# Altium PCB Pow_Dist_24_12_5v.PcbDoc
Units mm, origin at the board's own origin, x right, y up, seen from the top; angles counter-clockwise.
Board outline 255.4 x 262.89 mm, 2 copper layers (Top Layer, Bottom Layer); 118 components, 61 nets, 248 pads, 0 vias.
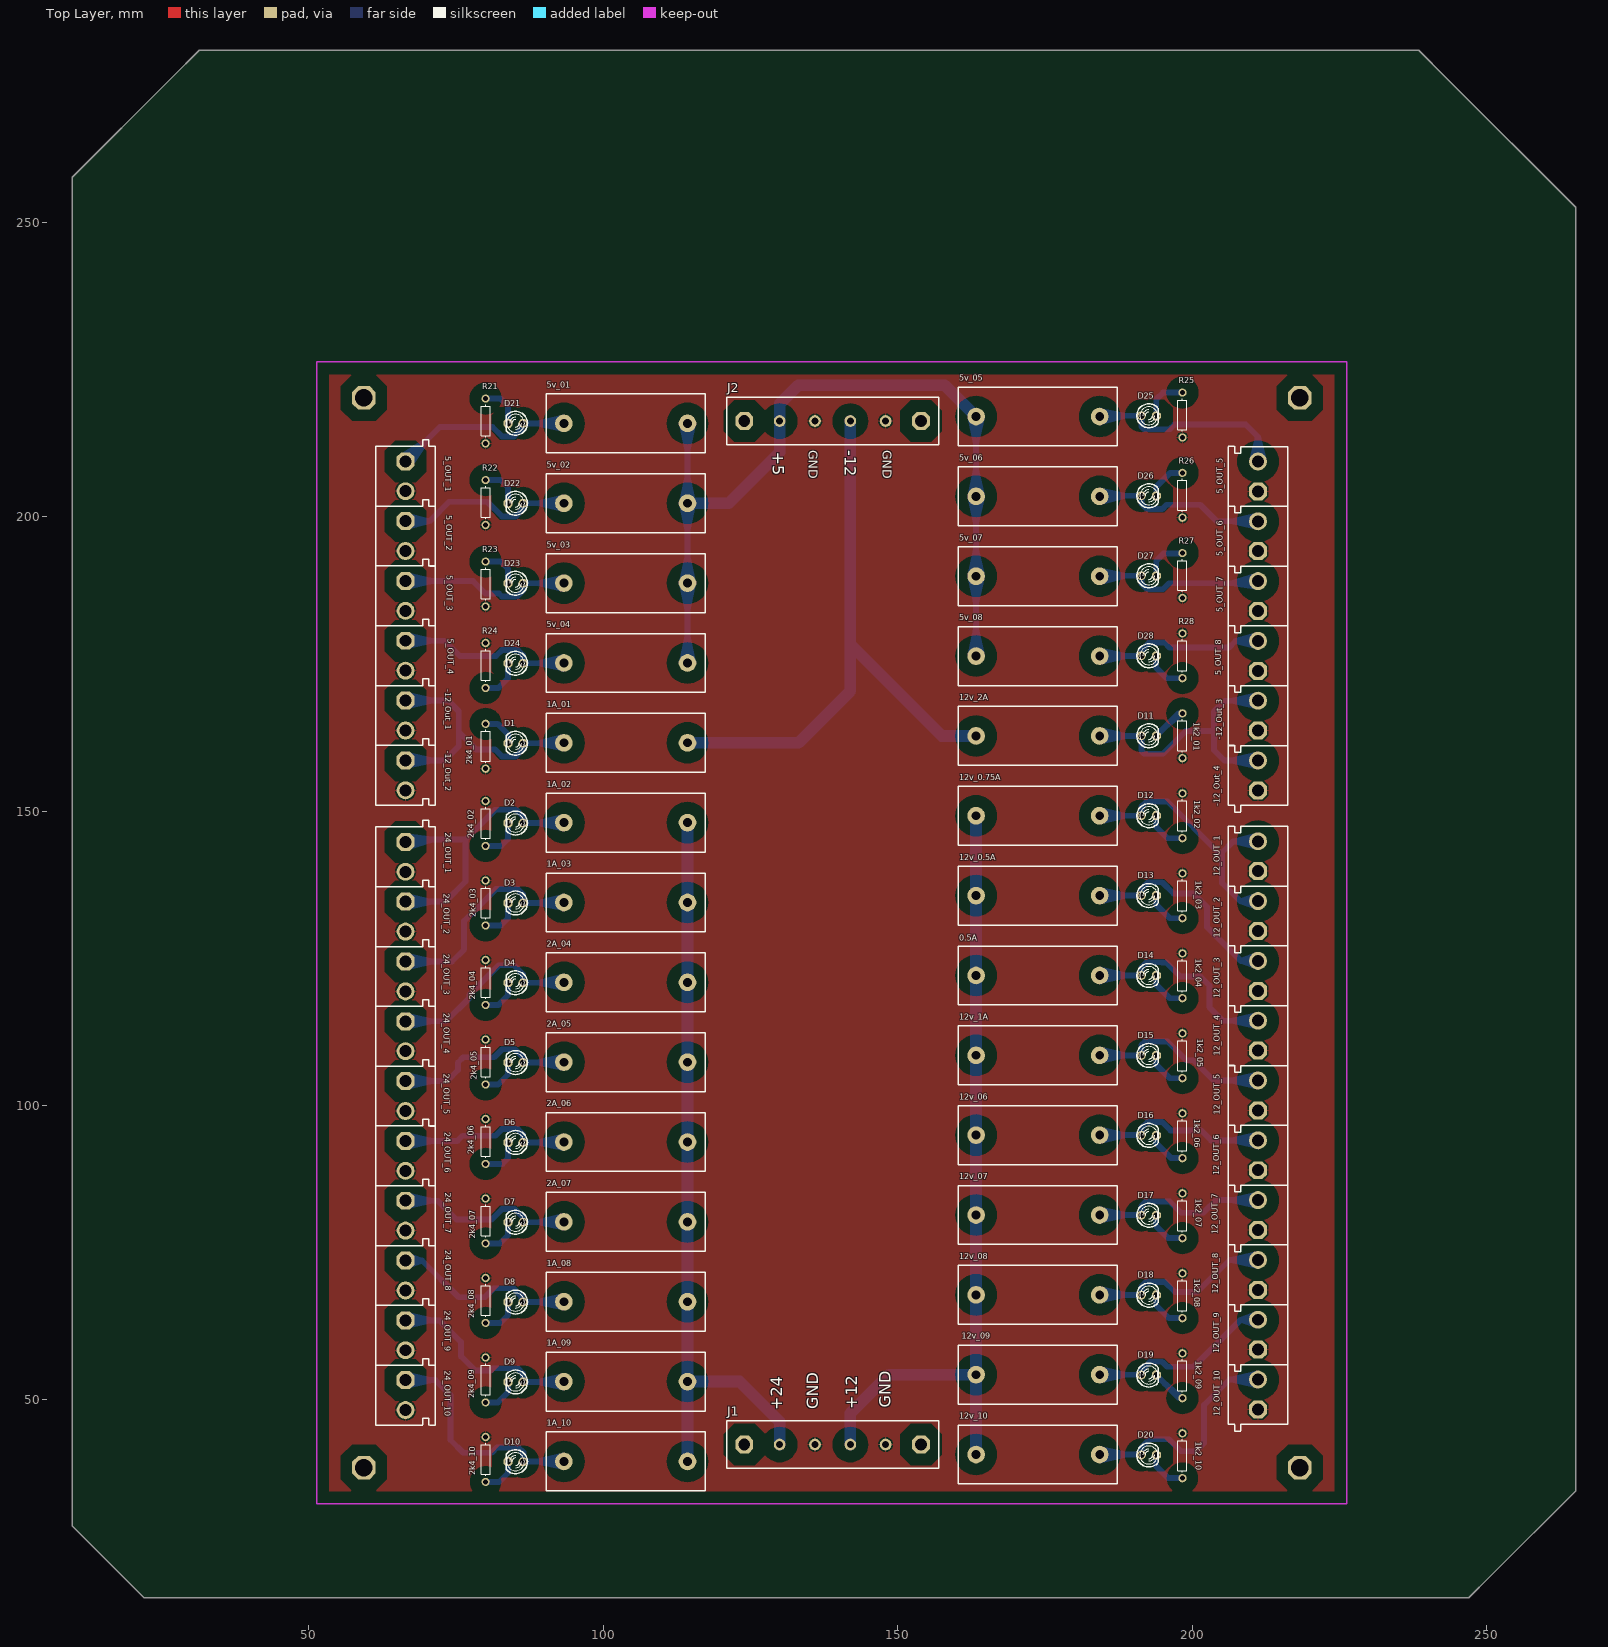
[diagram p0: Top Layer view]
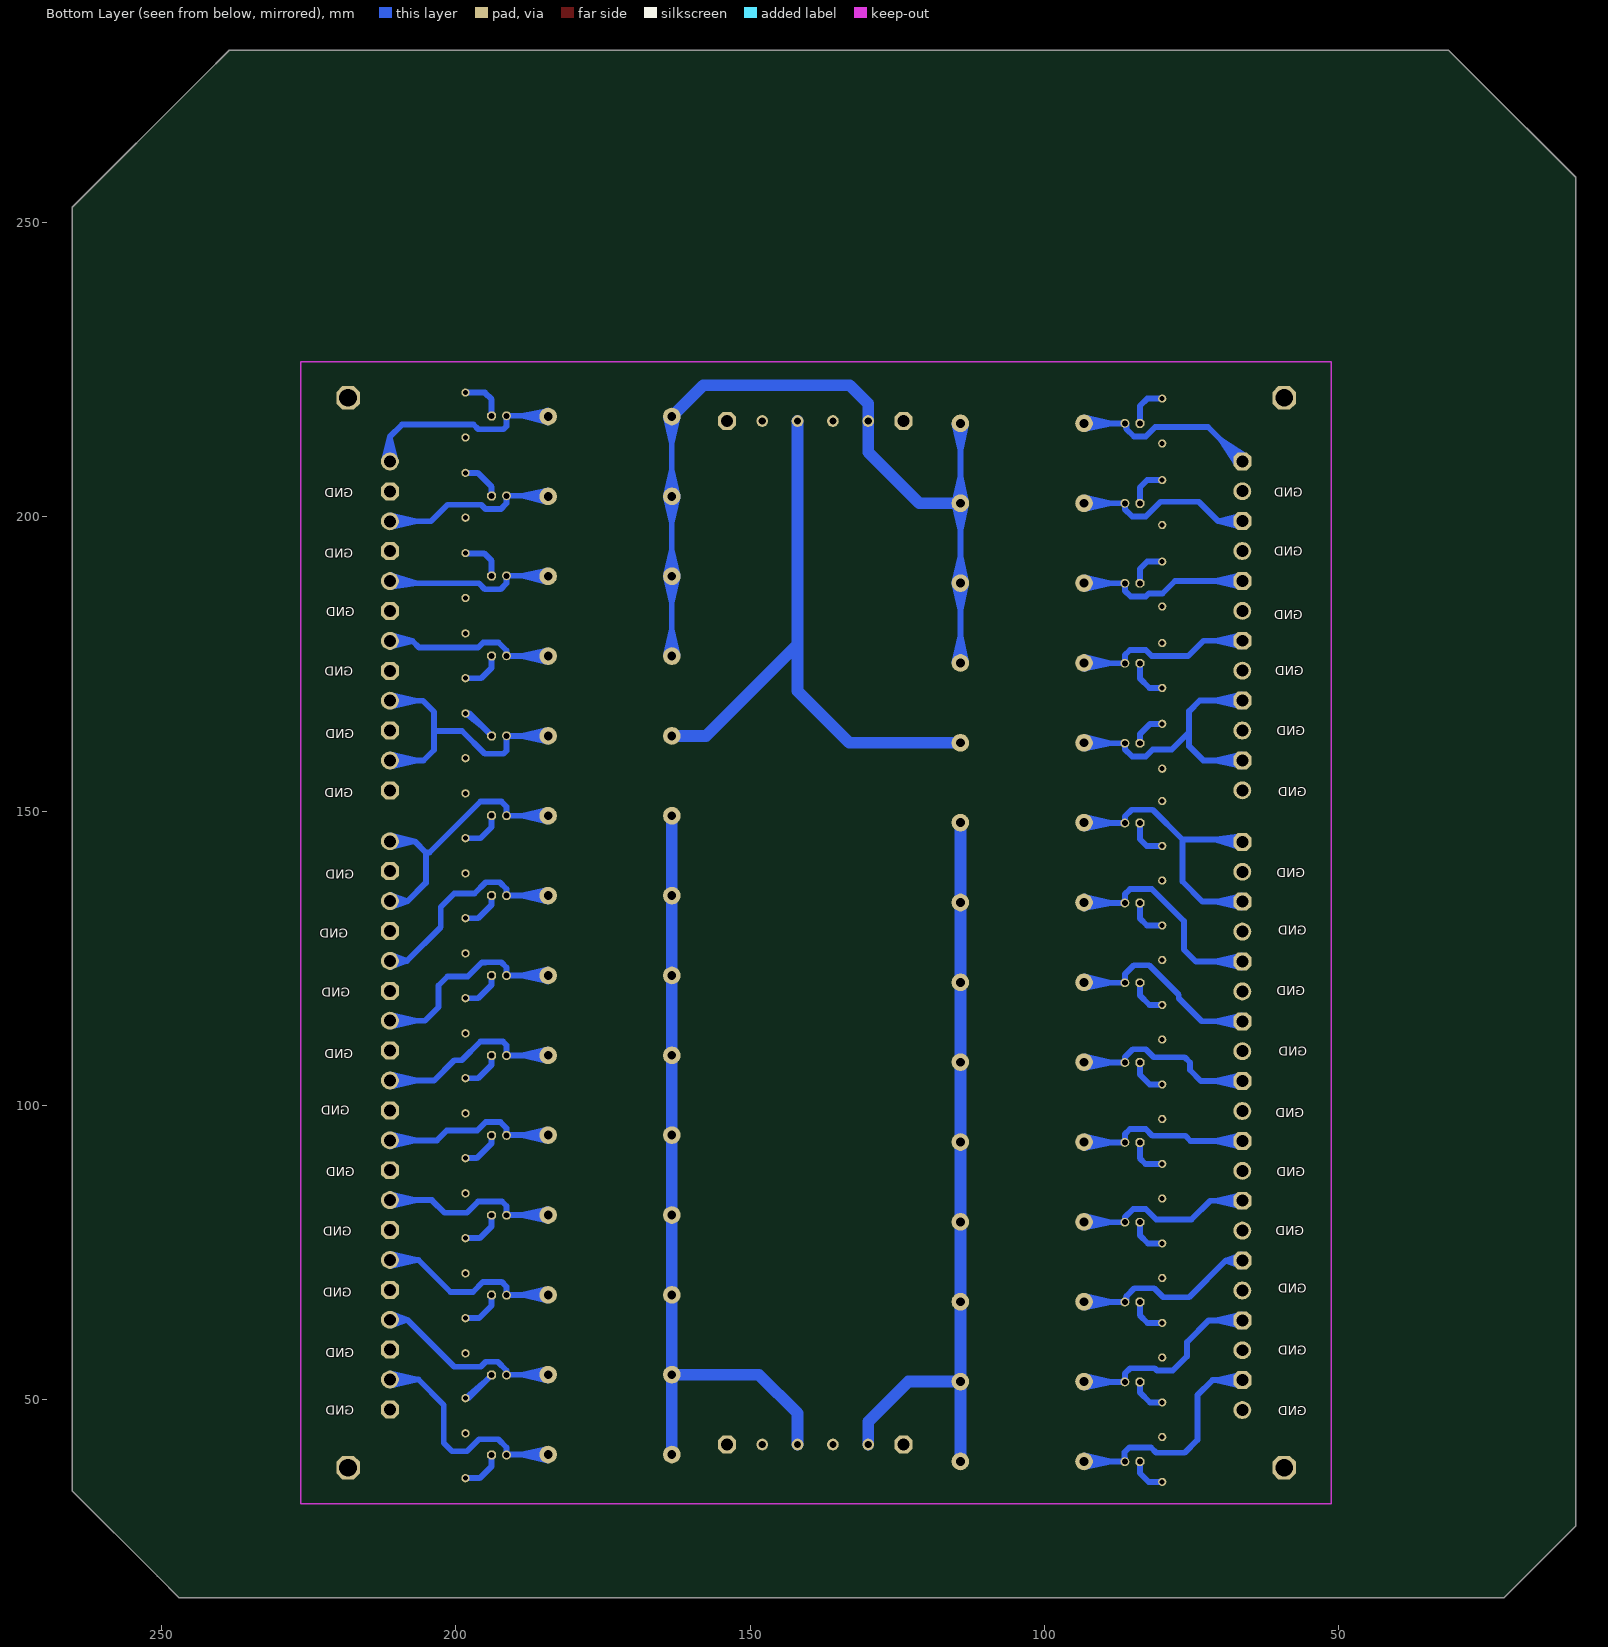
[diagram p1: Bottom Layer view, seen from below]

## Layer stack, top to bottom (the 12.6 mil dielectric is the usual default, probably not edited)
Top Solder: solder mask 0.0102, Solder Resist, Dk 3.5
Top Layer: signal copper 0.0356
Dielectric 1: dielectric 0.32, FR-4, Dk 4.8
Bottom Layer: signal copper 0.0356
Bottom Solder: solder mask 0.0102, Solder Resist, Dk 3.5

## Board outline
21.971,16.383 9.779,28.575 9.779,33.147 9.779,257.683 26.67,274.574 31.369,279.273 223.139,279.273 238.506,279.273 243.205,274.574 265.176,252.603 265.176,59.817 265.176,34.544 250.698,20.066 247.015,16.383 22.86,16.383

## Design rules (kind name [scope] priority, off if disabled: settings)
Clearance [All] p1: gap=1
PolygonConnect [All] p1: connectstyle=Relief reliefconductorwidth=0.254 reliefentries=4 polygonreliefangle="90 Angle" airgapwidth=0.254
RoutingVias [All] p1: holewidth=0.711 width=1.27 viastyle="Through Hole" minholewidth=0.711 minwidth=1.27 maxholewidth=0.711 maxwidth=1.27
SolderMaskExpansion [All] p1: expansion=0.102
Width [All] p1: maxlimit=2 minlimit=1 preferedwidth=1 minimp=50.000000 maximp=50.000000 favimp=50.000000
29 further rules are at their usual default settings.

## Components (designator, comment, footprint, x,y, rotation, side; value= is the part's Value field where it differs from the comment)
0.5A "Fuse 2" PCBComponent_1 163.322,122.098 r0 top
1A_01 "Fuse 2" PCBComponent_1 114.3,161.621 r180 top
1A_02 "Fuse 2" PCBComponent_1 114.3,148.058 r180 top
1A_03 "Fuse 2" PCBComponent_1 114.3,134.494 r180 top
1A_08 "Fuse 2" PCBComponent_1 114.3,66.675 r180 top
1A_09 "Fuse 2" PCBComponent_1 114.3,53.111 r180 top
1A_10 "Fuse 2" PCBComponent_1 114.3,39.547 r180 top
1k2_01 "Res1" AXIAL-0.3 198.374,162.814 r270 top
1k2_02 "Res1" AXIAL-0.3 198.374,149.225 r90 top
1k2_03 "Res1" AXIAL-0.3 198.374,135.636 r90 top
1k2_04 "Res1" AXIAL-0.3 198.374,122.047 r90 top
1k2_05 "Res1" AXIAL-0.3 198.374,108.458 r90 top
1k2_06 "Res1" AXIAL-0.3 198.374,94.869 r90 top
1k2_07 "Res1" AXIAL-0.3 198.374,81.28 r90 top
1k2_08 "Res1" AXIAL-0.3 198.374,67.691 r90 top
1k2_09 "Res1" AXIAL-0.3 198.374,54.102 r90 top
1k2_10 "Res1" AXIAL-0.3 198.374,40.513 r90 top
2A_04 "Fuse 2" PCBComponent_1 114.3,120.93 r180 top
2A_05 "Fuse 2" PCBComponent_1 114.3,107.366 r180 top
2A_06 "Fuse 2" PCBComponent_1 114.3,93.803 r180 top
2A_07 "Fuse 2" PCBComponent_1 114.3,80.239 r180 top
2k4_01 "Res1" AXIAL-0.3 80.01,161.036 r270 top
2k4_02 "Res1" AXIAL-0.3 80.01,147.913 r90 top
2k4_03 "Res1" AXIAL-0.3 80.01,134.408 r90 top
2k4_04 "Res1" AXIAL-0.3 80.01,120.904 r90 top
2k4_05 "Res1" AXIAL-0.3 80.01,107.4 r90 top
2k4_06 "Res1" AXIAL-0.3 80.01,93.895 r90 top
2k4_07 "Res1" AXIAL-0.3 80.01,80.391 r90 top
2k4_08 "Res1" AXIAL-0.3 80.01,66.887 r90 top
2k4_09 "Res1" AXIAL-0.3 80.01,53.382 r90 top
2k4_10 "Res1" AXIAL-0.3 80.01,39.878 r90 top
5_OUT_1 "CON2 pin blue" My_CN2 71.501,211.963 r270 top
5_OUT_2 "CON2 pin blue" My_CN2 71.501,201.803 r270 top
5_OUT_3 "CON2 pin blue" My_CN2 71.501,191.643 r270 top
5_OUT_4 "CON2 pin blue" My_CN2 71.501,181.483 r270 top
5_OUT_5 "CON2 pin blue" My_CN2 206.121,201.803 r90 top
5_OUT_6 "CON2 pin blue" My_CN2 206.121,191.643 r90 top
5_OUT_7 "CON2 pin blue" My_CN2 206.121,181.483 r90 top
5_OUT_8 "CON2 pin blue" My_CN2 206.121,171.323 r90 top
5v_01 "Fuse 2" PCBComponent_1 114.3,215.877 r180 top
5v_02 "Fuse 2" PCBComponent_1 114.3,202.313 r180 top
5v_03 "Fuse 2" PCBComponent_1 114.3,188.749 r180 top
5v_04 "Fuse 2" PCBComponent_1 114.3,175.185 r180 top
5v_05 "Fuse 2" PCBComponent_1 163.322,217.045 r0 top
5v_06 "Fuse 2" PCBComponent_1 163.322,203.481 r0 top
5v_07 "Fuse 2" PCBComponent_1 163.322,189.917 r0 top
5v_08 "Fuse 2" PCBComponent_1 163.322,176.353 r0 top
12_OUT_1 "CON2 pin blue" My_CN2 206.121,137.287 r90 top
12_OUT_2 "CON2 pin blue" My_CN2 206.121,127.127 r90 top
12_OUT_3 "CON2 pin blue" My_CN2 206.121,116.967 r90 top
12_OUT_4 "CON2 pin blue" My_CN2 206.121,106.807 r90 top
12_OUT_5 "CON2 pin blue" My_CN2 206.121,96.647 r90 top
12_OUT_6 "CON2 pin blue" My_CN2 206.121,86.487 r90 top
12_OUT_7 "CON2 pin blue" My_CN2 206.121,76.327 r90 top
12_OUT_8 "CON2 pin blue" My_CN2 206.121,66.167 r90 top
12_OUT_9 "CON2 pin blue" My_CN2 206.121,56.007 r90 top
12_OUT_10 "CON2 pin blue" My_CN2 206.121,45.847 r90 top
12v_0.5A "Fuse 2" PCBComponent_1 163.322,135.662 r0 top
12v_0.75A "Fuse 2" PCBComponent_1 163.322,149.226 r0 top
12v_1A "Fuse 2" PCBComponent_1 163.322,108.535 r0 top
12v_2A "Fuse 2" PCBComponent_1 163.322,162.79 r0 top
12v_06 "Fuse 2" PCBComponent_1 163.322,94.971 r0 top
12v_07 "Fuse 2" PCBComponent_1 163.322,81.407 r0 top
12v_08 "Fuse 2" PCBComponent_1 163.322,67.843 r0 top
12v_09 "Fuse 2" PCBComponent_1 163.322,54.279 r0 top
12v_10 "Fuse 2" PCBComponent_1 163.322,40.716 r0 top
24_OUT_1 "CON2 pin blue" My_CN2 71.501,147.32 r270 top
24_OUT_2 "CON2 pin blue" My_CN2 71.501,137.16 r270 top
24_OUT_3 "CON2 pin blue" My_CN2 71.501,127 r270 top
24_OUT_4 "CON2 pin blue" My_CN2 71.501,116.84 r270 top
24_OUT_5 "CON2 pin blue" My_CN2 71.501,106.68 r270 top
24_OUT_6 "CON2 pin blue" My_CN2 71.501,96.52 r270 top
24_OUT_7 "CON2 pin blue" My_CN2 71.501,86.36 r270 top
24_OUT_8 "CON2 pin blue" My_CN2 71.501,76.2 r270 top
24_OUT_9 "CON2 pin blue" My_CN2 71.501,66.04 r270 top
24_OUT_10 "CON2 pin blue" My_CN2 71.501,55.88 r270 top
-12_Out_1 "CON2 pin blue" My_CN2 71.501,171.323 r270 top
-12_Out_2 "CON2 pin blue" My_CN2 71.501,161.163 r270 top
-12_Out_3 "CON2 pin blue" My_CN2 206.121,161.163 r90 top
-12_Out_4 "CON2 pin blue" My_CN2 206.121,151.003 r90 top
D1 "LED" My_LED3MM 85.09,161.544 r180 top
D2 "LED" My_LED3MM 85.09,147.983 r180 top
D3 "LED" My_LED3MM 85.09,134.422 r180 top
D4 "LED" My_LED3MM 85.09,120.862 r180 top
D5 "LED" My_LED3MM 85.09,107.301 r180 top
D6 "LED" My_LED3MM 85.09,93.74 r180 top
D7 "LED" My_LED3MM 85.09,80.179 r180 top
D8 "LED" My_LED3MM 85.09,66.619 r180 top
D9 "LED" My_LED3MM 85.09,53.058 r180 top
D10 "LED" My_LED3MM 85.09,39.497 r180 top
D11 "LED" My_LED3MM 192.659,162.814 r0 top
D12 "LED" My_LED3MM 192.659,149.239 r0 top
D13 "LED" My_LED3MM 192.659,135.664 r0 top
D14 "LED" My_LED3MM 192.659,122.089 r0 top
D15 "LED" My_LED3MM 192.659,108.514 r0 top
D16 "LED" My_LED3MM 192.659,94.94 r0 top
D17 "LED" My_LED3MM 192.659,81.365 r0 top
D18 "LED" My_LED3MM 192.659,67.79 r0 top
D19 "LED" My_LED3MM 192.659,54.215 r0 top
D20 "LED" My_LED3MM 192.659,40.64 r0 top
D21 "LED" My_LED3MM 85.09,215.9 r180 top
D22 "LED" My_LED3MM 85.09,202.311 r180 top
D23 "LED" My_LED3MM 85.09,188.722 r180 top
D24 "LED" My_LED3MM 85.09,175.133 r180 top
D25 "LED" My_LED3MM 192.659,217.17 r0 top
D26 "LED" My_LED3MM 192.659,203.581 r0 top
D27 "LED" My_LED3MM 192.659,189.992 r0 top
D28 "LED" My_LED3MM 192.659,176.403 r0 top
J1 "conn_4pin" conn_4pin 147.955,42.418 r180 top
J2 "conn_4pin" conn_4pin 147.955,216.281 r180 top
R21 "Res1" AXIAL-0.3 80.01,216.281 r270 top
R22 "Res1" AXIAL-0.3 80.01,202.438 r270 top
R23 "Res1" AXIAL-0.3 80.01,188.595 r270 top
R24 "Res1" AXIAL-0.3 80.01,174.752 r90 top
R25 "Res1" AXIAL-0.3 198.374,217.297 r270 top
R26 "Res1" AXIAL-0.3 198.374,203.666 r270 top
R27 "Res1" AXIAL-0.3 198.374,190.034 r270 top
R28 "Res1" AXIAL-0.3 198.374,176.403 r90 top

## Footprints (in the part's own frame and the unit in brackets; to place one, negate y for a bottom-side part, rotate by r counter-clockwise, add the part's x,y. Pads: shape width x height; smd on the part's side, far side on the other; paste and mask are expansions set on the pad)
AXIAL-0.3 [mm] "Axial Device, Thru-Hole; 2 Leads; 0.3 in Pin Spacing"
  round 1.4 hole 0.85: 1(-3.81,0) 2(3.81,0)
  silkscreen extent -2.77,-0.76 2.77,0.76
conn_4pin [mm]
  oct 3x3 hole 2: 0(-6,0) 5(24,0)
  round 2 hole 1.2: 1(0,0) 2(6,0) 3(12,0) 4(18,0)
  silkscreen extent -9,-4 27,4
My_CN2 [mil]
  oct 120x120 hole 80: 1(99.5,-200.5)
  round 120 hole 80: 2(299.5,-200.5)
  silkscreen extent -45,-400 400,0
My_LED3MM [mil]
  round 60 hole 40: A(-50,0)
  oct 60x60 hole 40: K(50,0)
  silkscreen extent -80,-80 62,80
PCBComponent_1 [mm]
  round 3 hole 1.5: 1(0,0) 2(21,0)
  silkscreen extent -3,-5 24,5

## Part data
0.5A 1A_01 1A_02 1A_03 1A_08 1A_09 1A_10 2A_04 2A_05 2A_06 2A_07 5v_01 5v_02 5v_03 5v_04 5v_05 5v_06 5v_07 5v_08 12v_0.5A 12v_0.75A 12v_1A 12v_2A 12v_06 12v_07 12v_08 12v_09 12v_10: "Fuse"
1k2_01 1k2_02 1k2_03 1k2_04 1k2_05 1k2_06 1k2_07 1k2_08 1k2_09 1k2_10 2k4_01 2k4_02 2k4_03 2k4_04 2k4_05 2k4_06 2k4_07 2k4_08 2k4_09 2k4_10 R21 R22 R23 R24 R25 R26 R27 R28: "Resistor"
5_OUT_1 5_OUT_2 5_OUT_3 5_OUT_4 5_OUT_5 5_OUT_6 5_OUT_7 5_OUT_8 12_OUT_1 12_OUT_2 12_OUT_3 12_OUT_4 12_OUT_5 12_OUT_6 12_OUT_7 12_OUT_8 12_OUT_9 12_OUT_10 24_OUT_1 24_OUT_2 24_OUT_3 24_OUT_4 24_OUT_5 24_OUT_6 24_OUT_7 24_OUT_8 24_OUT_9 24_OUT_10 -12_Out_1 -12_Out_2 -12_Out_3 -12_Out_4: "Connector blue screw"
D1 D2 D3 D4 D5 D6 D7 D8 D9 D10 D11 D12 D13 D14 D15 D16 D17 D18 D19 D20 D21 D22 D23 D24 D25 D26 D27 D28: "Typical INFRARED GaAs LED"

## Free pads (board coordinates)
  oct 4x4 hole 3: 3(59.309,38.481) 3(59.309,220.218) 3(218.313,38.481) 3(218.313,220.218)

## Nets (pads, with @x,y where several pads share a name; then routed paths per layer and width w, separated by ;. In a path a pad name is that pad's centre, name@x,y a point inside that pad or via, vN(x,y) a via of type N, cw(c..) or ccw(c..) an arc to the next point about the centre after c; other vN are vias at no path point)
GND: 1k2_01.2 1k2_02.2 1k2_03.2 1k2_04.2 1k2_05.2 1k2_06.2 1k2_07.2 1k2_08.2 1k2_09.2 1k2_10.2 2k4_01.2 2k4_02.2 2k4_03.2 2k4_04.2 2k4_05.2 2k4_06.2 2k4_07.2 2k4_08.2 2k4_09.2 2k4_10.2 5_OUT_1.2 5_OUT_2.2 5_OUT_3.2 5_OUT_4.2 5_OUT_5.1 5_OUT_6.1 5_OUT_7.1 5_OUT_8.1 12_OUT_1.1 12_OUT_2.1 12_OUT_3.1 12_OUT_4.1 12_OUT_5.1 12_OUT_6.1 12_OUT_7.1 12_OUT_8.1 12_OUT_9.1 12_OUT_10.1 24_OUT_1.2 24_OUT_2.2 24_OUT_3.2 24_OUT_4.2 24_OUT_5.2 24_OUT_6.2 24_OUT_7.2 24_OUT_8.2 24_OUT_9.2 24_OUT_10.2 -12_Out_1.2 -12_Out_2.2 -12_Out_3.1 -12_Out_4.1 J1.1 J1.3 J2.1 J2.3 R21.2 R22.2 R23.2 R24.2 R25.2 R26.2 R27.2 R28.2
Net0.5A_1: 0.5A.1 12v_0.5A.1 12v_0.75A.1 12v_1A.1 12v_06.1 12v_07.1 12v_08.1 12v_09.1 12v_10.1 J1.2 | length 137.9
  Bottom Layer w2: J1.2 141.955,47.721 148.513,54.279 12v_09.1 ; 12v_10.1 12v_09.1 ; 12v_0.75A.1 12v_0.5A.1 0.5A.1 12v_1A.1 12v_06.1 12v_07.1 12v_08.1 12v_09.1
Net0.5A_2: 0.5A.2 12_OUT_4.2 D14.A | length 56.7
  Bottom Layer w1: 0.5A.2 191.38,122.098 D14.A ; 0.5A.2@184.433,121.105 188.822,122.098 0.5A.2@184.433,123.092 ; 187.627,122.098 D14.A ; 12_OUT_4.2@211.098,113.397 206.69,114.414 12_OUT_4.2@211.098,115.432 ; 12_OUT_4.2 205.245,114.414 202.946,116.713 202.946,120.396 201.422,121.92 197.993,121.92 195.58,124.333 194.95,124.333 194.931,124.351 192.296,124.351 191.389,123.444 D14.A
Net1A_01_1: 1A_01.1 12v_2A.1 J2.2 | length 105
  Bottom Layer w2: 1A_01.1 133.173,161.621 141.955,170.403 141.955,178.339 ; J2.2 141.955,178.339 ; 12v_2A.1 157.504,162.79 141.955,178.339
Net1A_02_1: 1A_02.1 1A_03.1 1A_08.1 1A_09.1 1A_10.1 2A_04.1 2A_05.1 2A_06.1 2A_07.1 J1.4 | length 130.9
  Bottom Layer w2: 1A_10.1 1A_09.1 ; 1A_02.1 1A_03.1 2A_04.1 2A_05.1 2A_06.1 2A_07.1 1A_08.1 1A_09.1 ; J1.4 129.955,46.321 123.165,53.111 1A_09.1
Net1A_02_2: 1A_02.2 24_OUT_1.1 24_OUT_2.1 D2.A | length 86.8
  Bottom Layer w1: 24_OUT_2.1 73.165,134.633 76.581,138.049 76.581,145.182 ; 24_OUT_1.1@66.436,145.816 70.98,145.182 ; 24_OUT_2.1@66.524,133.615 70.932,134.633 24_OUT_2.1@66.524,135.65 ; 24_OUT_1.1@66.609,143.788 70.98,145.182 ; 1A_02.2@93.173,149.05 88.799,147.983 ; 1A_02.2@93.205,147.062 88.799,147.983 ; 1A_02.2@93.226,147.983 D2.A ; 1A_02.2 88.799,147.983 ; 70.98,145.182 24_OUT_1.1 66.798,145.182 76.581,145.182 ; 76.581,145.182 81.644,150.245 85.213,150.245 86.36,149.098 ; D2.A 86.36,149.098 ; D2.A 86.36,149.098
Net1A_03_2: 1A_03.2 24_OUT_3.1 D3.A | length 59.2
  Bottom Layer w1: 24_OUT_3.1 74.308,124.473 76.327,126.492 76.327,131.318 81.788,136.779 85.471,136.779 86.36,135.89 D3.A 93.229,134.422 1A_03.2 88.799,134.422 ; 24_OUT_3.1@66.524,123.455 70.932,124.473 24_OUT_3.1@66.524,125.49 ; 1A_03.2@93.173,135.486 88.799,134.422 ; 1A_03.2@93.205,133.498 88.799,134.422
Net1A_08_2: 1A_08.2 24_OUT_8.1 D8.A | length 52.7
  Bottom Layer w1: 24_OUT_8.1 69.202,73.673 ; 24_OUT_8.1@66.596,72.666 69.202,73.673 ; 24_OUT_8.1@66.596,74.679 69.202,73.673 ; 1A_08.2@93.176,67.667 88.799,66.619 ; 1A_08.2@93.201,65.68 88.799,66.619 ; 69.202,73.673 75.438,67.437 79.862,67.437 81.386,68.961 84.742,68.961 86.082,67.621 ; 86.082,67.621 D8.A ; 86.082,67.621 D8.A ; 86.082,67.621 86.082,66.897 D8.A ; D8.A 93.244,66.619 1A_08.2 88.799,66.619
Net1A_09_2: 1A_09.2 24_OUT_9.1 D9.A | length 56.4
  Bottom Layer w1: 24_OUT_9.1 72.123,63.513 75.819,59.817 75.819,57.404 78.231,54.992 80.921,54.992 81.301,55.372 85.471,55.372 86.36,54.483 D9.A 93.247,53.058 1A_09.2 88.799,53.058 ; 24_OUT_9.1@66.524,62.495 70.932,63.513 24_OUT_9.1@66.524,64.53 ; 1A_09.2@93.177,54.104 88.799,53.058 ; 1A_09.2@93.201,52.116 88.799,53.058
Net1A_10_2: 1A_10.2 24_OUT_10.1 D10.A | length 62.1
  Bottom Layer w1: 24_OUT_10.1 71.488,53.353 74.041,50.8 74.041,43.18 76.2,41.021 81.026,41.021 81.915,41.91 85.598,41.91 86.41,41.098 ; 24_OUT_10.1@66.524,52.335 70.932,53.353 24_OUT_10.1@66.524,54.37 ; 90.123,39.547 D10.A 86.41,41.098 ; 1A_10.2@93.189,38.554 88.8,39.547 1A_10.2@93.189,40.541 ; 1A_10.2 86.41,39.547 86.41,41.098
Net1k2_01_1: 1k2_01.1 D11.K | length 10.1
  Bottom Layer w1: D11.K 197.739,166.624 1k2_01.1 195.191,164.076
Net1k2_02_1: 1k2_02.1 D12.K | length 11.6
  Bottom Layer w1: 193.929,147.32 D12.K 193.929,147.32 ; 193.929,147.32 195.834,145.415 ; 195.834,145.415 1k2_02.1 195.834,145.415
Net1k2_03_1: 1k2_03.1 D13.K | length 10.7
  Bottom Layer w1: 193.929,134.112 D13.K 193.929,134.112 ; 193.929,134.112 196.215,131.826 ; 196.215,131.826 1k2_03.1 196.215,131.826
Net1k2_04_1: 1k2_04.1 D14.K | length 8.5
  Bottom Layer w1: 1k2_04.1 196.215,118.237 193.929,120.523 ; 193.929,120.523 D14.K 193.929,120.523
Net1k2_05_1: 1k2_05.1 D15.K | length 10.7
  Bottom Layer w1: 193.929,106.934 D15.K 193.929,106.934 ; 193.929,106.934 196.215,104.648 ; 196.215,104.648 1k2_05.1 196.215,104.648
Net1k2_06_1: 1k2_06.1 D16.K | length 8.2
  Bottom Layer w1: 1k2_06.1 196.469,91.059 193.929,93.599 ; 193.929,93.599 D16.K 193.929,93.599
Net1k2_07_1: 1k2_07.1 D17.K | length 9
  Bottom Layer w1: 1k2_07.1 195.961,77.47 193.929,79.502 ; 193.929,79.502 D17.K 193.929,79.502
Net1k2_08_1: 1k2_08.1 D18.K | length 11.1
  Bottom Layer w1: 193.929,66.04 D18.K 193.929,66.04 ; 193.929,66.04 196.088,63.881 ; 196.088,63.881 1k2_08.1 196.088,63.881
Net1k2_09_1: 1k2_09.1 D19.K | length 10.1
  Bottom Layer w1: D19.K 197.852,50.292 1k2_09.1 195.276,52.868
Net1k2_10_1: 1k2_10.1 D20.K | length 9.1
  Bottom Layer w1: 1k2_10.1 195.961,36.703 193.929,38.735 ; 193.929,38.735 D20.K 193.929,38.735
Net2A_04_2: 2A_04.2 24_OUT_4.1 D4.A | length 55.8
  Bottom Layer w1: 24_OUT_4.1 73.292,114.313 77.216,118.237 77.216,118.809 82.232,123.825 84.836,123.825 86.36,122.301 D4.A 93.232,120.862 2A_04.2 88.799,120.862 ; 24_OUT_4.1@66.524,113.295 70.932,114.313 24_OUT_4.1@66.524,115.33 ; 2A_04.2@93.174,121.922 88.799,120.862 ; 2A_04.2@93.204,119.935 88.799,120.862
Net2A_05_2: 2A_05.2 24_OUT_5.1 D5.A | length 54.7
  Bottom Layer w1: 24_OUT_5.1 73.419,104.153 75.311,106.045 75.311,107.315 76.2,108.204 81.459,108.204 82.818,109.563 85.001,109.563 86.36,108.204 ; 24_OUT_5.1@66.524,103.135 70.932,104.153 24_OUT_5.1@66.524,105.17 ; 2A_05.2@93.174,108.358 88.799,107.301 ; 2A_05.2@93.203,106.371 88.799,107.301 ; 2A_05.2@93.235,107.301 D5.A ; 2A_05.2 88.799,107.301 ; D5.A 86.36,108.204 ; D5.A 86.36,108.204
Net2A_06_2: 2A_06.2 24_OUT_6.1 D6.A | length 52
  Bottom Layer w1: 24_OUT_6.1 75.197,93.993 76.073,94.869 81.685,94.869 82.818,96.002 85.481,96.002 86.36,95.123 D6.A 93.238,93.74 2A_06.2 88.799,93.74 ; 24_OUT_6.1@66.524,92.975 70.932,93.993 24_OUT_6.1@66.524,95.01 ; 2A_06.2@93.175,94.795 88.799,93.74 ; 2A_06.2@93.203,92.807 88.799,93.74
Net2A_07_2: 2A_07.2 24_OUT_7.1 D7.A | length 53.8
  Bottom Layer w1: 24_OUT_7.1 71.869,83.833 75.057,80.645 81.021,80.645 82.818,82.441 84.945,82.441 86.36,81.026 ; 24_OUT_7.1@66.524,82.815 70.932,83.833 24_OUT_7.1@66.524,84.85 ; 2A_07.2@93.176,81.231 88.799,80.179 ; 2A_07.2@93.202,79.244 88.799,80.179 ; D7.A 86.36,81.026 ; D7.A 93.241,80.179 2A_07.2 88.799,80.179 ; D7.A 86.36,81.026
Net2k4_01_1: 2k4_01.1 D1.K | length 6.1
  Bottom Layer w1: 2k4_01.1 82.042,164.846 83.82,163.068 D1.K
Net2k4_02_1: 2k4_02.1 D2.K | length 9.7
  Bottom Layer w1: 2k4_02.1 82.635,144.103 83.82,145.288 ; 83.82,145.288 D2.K 83.82,145.288
Net2k4_03_1: 2k4_03.1 D3.K | length 9.5
  Bottom Layer w1: 2k4_03.1 82.592,130.598 83.82,131.826 ; 83.82,131.826 D3.K 83.82,131.826
Net2k4_04_1: 2k4_04.1 D4.K | length 8.7
  Bottom Layer w1: 2k4_04.1 82.169,117.094 83.82,118.745 ; 83.82,118.745 D4.K 83.82,118.745
Net2k4_05_1: 2k4_05.1 D5.K | length 8.5
  Bottom Layer w1: 2k4_05.1 82.127,103.59 83.82,105.283 ; 83.82,105.283 D5.K 83.82,105.283
Net2k4_06_1: 2k4_06.1 D6.K | length 9.6
  Bottom Layer w1: 2k4_06.1 82.846,90.085 83.82,91.059 ; 83.82,91.059 D6.K 83.82,91.059
Net2k4_07_1: 2k4_07.1 D7.K | length 8.8
  Bottom Layer w1: 2k4_07.1 82.423,76.581 83.82,77.978 ; 83.82,77.978 D7.K 83.82,77.978
Net2k4_08_1: 2k4_08.1 D8.K | length 8.8
  Bottom Layer w1: 2k4_08.1 82.508,63.077 83.82,64.389 ; 83.82,64.389 D8.K 83.82,64.389
Net2k4_09_1: 2k4_09.1 D9.K | length 8
  Bottom Layer w1: 2k4_09.1 82.084,49.572 83.82,51.308 ; 83.82,51.308 D9.K 83.82,51.308
Net2k4_10_1: 2k4_10.1 D10.K | length 8.3
  Bottom Layer w1: 2k4_10.1 82.296,36.068 83.82,37.592 ; 83.82,37.592 D10.K 83.82,37.592
Net5_OUT_1_1: 5_OUT_1.1 5v_01.2 D21.A | length 53
  Bottom Layer w1: 5_OUT_1.1@65.76,210.228 70.054,213.081 5_OUT_1.1@67.201,208.787 ; 5_OUT_1.1 72.238,215.265 81.191,215.265 82.818,213.638 84.822,213.638 86.082,214.898 ; 5v_01.2@93.189,214.883 88.8,215.877 5v_01.2@93.189,216.87 ; 5v_01.2 D21.A@86.487,215.877 ; 86.082,214.898 D21.A ; 86.082,214.898 D21.A ; 86.082,214.898 86.082,215.622 D21.A ; D21.A@86.487,215.877 86.487,215.773 86.383,215.877 D21.A@86.487,215.877
Net5_OUT_2_1: 5_OUT_2.1 5v_02.2 D22.A | length 53.5
  Bottom Layer w1: 5_OUT_2.1 70.498,199.276 ; 5_OUT_2.1@66.537,198.26 70.498,199.276 ; 5_OUT_2.1@66.537,200.292 70.498,199.276 ; 5v_02.2@93.189,201.319 88.8,202.311 ; 5v_02.2@93.188,203.307 88.8,202.311 ; 5v_02.2@93.298,202.311 D22.A ; 5v_02.2 88.8,202.311 ; 70.498,199.276 73.787,202.565 80.302,202.565 82.818,200.049 85.114,200.049 86.36,201.295 ; 86.36,201.295 D22.A ; 86.36,201.295 D22.A
Net5_OUT_3_1: 5_OUT_3.1 5v_03.2 D23.A | length 52.2
  Bottom Layer w1: 5_OUT_3.1 77.838,189.116 79.969,186.985 82.293,186.985 82.818,186.46 85.368,186.46 86.36,187.452 D23.A 5v_03.2@93.273,188.722 ; 5_OUT_3.1@66.524,188.098 70.932,189.116 5_OUT_3.1@66.524,190.133 ; 5v_03.2@93.183,189.742 88.8,188.722 ; 5v_03.2@93.195,187.755 88.8,188.722 ; 5v_03.2 88.8,188.722
Net5_OUT_4_1: 5_OUT_4.1 5v_04.2 D24.A | length 52.6
  Bottom Layer w1: 5_OUT_4.1 73.012,178.956 75.606,176.362 81.785,176.362 82.818,177.395 85.495,177.395 86.36,176.53 D24.A 5v_04.2@93.248,175.133 ; 5_OUT_4.1@66.524,177.938 70.932,178.956 5_OUT_4.1@66.524,179.973 ; 5v_04.2@93.177,176.178 88.799,175.133 ; 5v_04.2@93.2,174.19 88.799,175.133 ; 5v_04.2 88.799,175.133
Net5_OUT_5_2: 5_OUT_5.2 5v_05.2 D25.A | length 56
  Bottom Layer w1: 5v_05.2 188.826,217.17 ; 5v_05.2@184.405,218.041 188.826,217.17 ; 5v_05.2@184.447,217.17 D25.A 191.389,215.392 191.897,214.884 196.215,214.884 197.018,215.687 209.128,215.687 211.214,213.601 ; 5v_05.2@184.461,216.054 188.826,217.17 ; 5_OUT_5.2@210.197,209.535 211.214,213.601 ; 5_OUT_5.2 211.214,213.601 ; 5_OUT_5.2@212.23,209.535 211.214,213.601
Net5_OUT_6_2: 5_OUT_6.2 5v_06.2 D26.A | length 52.6
  Bottom Layer w1: 5v_06.2@184.411,204.477 188.824,203.581 ; 5v_06.2@184.455,202.49 188.824,203.581 ; 5_OUT_6.2@211.098,198.233 206.69,199.25 5_OUT_6.2@211.098,200.268 ; 5_OUT_6.2 204.229,199.25 201.423,202.056 195.668,202.056 194.931,201.319 192.381,201.319 191.389,202.311 D26.A 184.422,203.581 5v_06.2 188.824,203.581
Net5_OUT_7_2: 5_OUT_7.2 5v_07.2 D27.A | length 56.3
  Bottom Layer w1: 5v_07.2 188.823,189.992 ; 5v_07.2@184.397,189.992 D27.A 191.389,188.722 192.405,187.706 195.072,187.706 196.088,188.722 210.845,188.722 5_OUT_7.2 206.643,188.722 ; 5v_07.2@184.417,190.913 188.823,189.992 ; 5v_07.2@184.45,188.925 188.823,189.992 ; 5_OUT_7.2@211.018,190.095 206.643,188.722 ; 5_OUT_7.2@211.181,188.067 206.643,188.722
Net5_OUT_8_2: 5_OUT_8.2 5v_08.2 D28.A | length 50.5
  Bottom Layer w1: 5v_08.2 D28.A@191.339,176.353 ; 5v_08.2@184.433,175.36 188.822,176.353 5v_08.2@184.433,177.347 ; 187.626,176.353 D28.A ; 5_OUT_8.2@211.077,177.915 207.378,178.93 ; 5_OUT_8.2@211.077,179.945 207.378,178.93 ; 5_OUT_8.2 207.378,178.93 ; D28.A 191.389,177.292 ; D28.A 191.389,177.292 ; 191.389,177.292 192.762,178.665 195.35,178.665 196.228,177.787 206.235,177.787 207.378,178.93
Net5v_01_1: 5v_01.1 5v_02.1 5v_03.1 5v_04.1 5v_05.1 5v_06.1 5v_07.1 5v_08.1 J2.4 | length 253.8
  Bottom Layer w1: 5v_04.1@113.306,175.296 114.3,179.685 5v_04.1@115.294,175.296 ; 5v_03.1@113.306,188.638 114.3,184.249 5v_03.1@115.294,188.638 ; 5v_03.1@113.306,188.86 114.3,193.249 5v_03.1@115.294,188.86 ; 5v_02.1@113.306,202.202 114.3,197.813 5v_02.1@115.294,202.202 ; 5v_02.1@113.306,202.424 114.3,206.813 5v_02.1@115.294,202.424 ; 5v_01.1@113.306,215.765 114.3,211.377 5v_01.1@115.294,215.765 ; 5v_04.1 5v_03.1 5v_02.1 5v_01.1 ; 5v_08.1@162.328,176.465 163.322,180.853 5v_08.1@164.316,176.465 ; 5v_07.1@162.328,189.806 163.322,185.417 5v_07.1@164.316,189.806 ; 5v_07.1@162.328,190.028 163.322,194.417 5v_07.1@164.316,190.028 ; 5v_06.1@162.328,203.37 163.322,198.981 5v_06.1@164.316,203.37 ; 5v_06.1@162.328,203.592 163.322,207.981 5v_06.1@164.316,203.592 ; 5v_05.1@162.328,216.934 163.322,212.545 5v_05.1@164.316,216.934 ; 5v_08.1 5v_07.1 5v_06.1 5v_05.1
  Bottom Layer w2: 5v_02.1 121.287,202.313 129.955,210.981 J2.4 129.955,219.236 133.096,222.377 157.99,222.377 5v_05.1
Net12_OUT_1_2: 12_OUT_1.2 12_OUT_2.2 12v_0.75A.2 D12.A | length 72.9
  Bottom Layer w1: 12v_0.75A.2 D12.A@191.376,149.226 ; 12v_0.75A.2@184.433,148.232 188.822,149.226 12v_0.75A.2@184.433,150.22 ; 187.627,149.226 D12.A 191.389,150.749 192.278,151.638 195.834,151.638 204.47,143.002 205.105,143.002 ; 12_OUT_2.2@211.04,133.725 208.2,134.734 ; 12_OUT_2.2@211.04,135.743 208.2,134.734 ; 12_OUT_1.2@211.089,143.878 206.997,144.894 ; 12_OUT_1.2@211.089,145.911 206.997,144.894 ; 12_OUT_2.2 208.2,134.734 ; 12_OUT_1.2 206.997,144.894 ; 205.105,143.002 206.997,144.894 ; 205.105,143.002 205.105,137.829 208.2,134.734
Net12_OUT_3_2: 12_OUT_3.2 12v_0.5A.2 D13.A | length 55.7
  Bottom Layer w1: 12v_0.5A.2 D13.A@191.387,135.662 ; 12v_0.5A.2@184.433,134.668 188.822,135.662 12v_0.5A.2@184.433,136.656 ; 187.627,135.662 D13.A ; 12_OUT_3.2@211.034,123.566 208.293,124.574 ; 12_OUT_3.2@211.034,125.582 208.293,124.574 ; 12_OUT_3.2 208.293,124.574 ; D13.A 191.389,136.779 ; D13.A 191.389,136.779 ; 191.389,136.779 192.536,137.926 194.931,137.926 196.841,136.017 200.279,136.017 202.565,133.731 202.565,130.302 208.293,124.574
Net12_OUT_5_2: 12_OUT_5.2 12v_1A.2 D15.A | length 53.4
  Bottom Layer w1: 12v_1A.2 D15.A@191.369,108.535 ; 12v_1A.2@184.433,107.541 188.822,108.535 12v_1A.2@184.433,109.528 ; 187.627,108.535 D15.A 191.389,110.236 192.024,110.871 195.834,110.871 199.009,107.696 200.254,107.696 203.695,104.254 12_OUT_5.2 ; 12_OUT_5.2@211.098,103.237 206.69,104.254 12_OUT_5.2@211.098,105.272
Net12_OUT_6_2: 12_OUT_6.2 12v_06.2 D16.A | length 52.8
  Bottom Layer w1: 12v_06.2 D16.A@191.358,94.971 ; 12v_06.2@184.433,93.977 188.822,94.971 12v_06.2@184.433,95.965 ; 187.626,94.971 D16.A ; 12_OUT_6.2@211.098,93.077 206.69,94.094 12_OUT_6.2@211.098,95.112 ; 12_OUT_6.2 203.213,94.094 201.549,95.758 196.375,95.758 194.931,97.202 192.452,97.202 191.389,96.139 ; D16.A 191.389,96.139 ; D16.A 191.389,96.139
Net12_OUT_7_2: 12_OUT_7.2 12v_07.2 D17.A | length 52.3
  Bottom Layer w1: 12v_07.2 191.347,81.407 D17.A ; 12v_07.2@184.433,80.413 188.822,81.407 12v_07.2@184.433,82.401 ; 187.626,81.407 D17.A ; 12_OUT_7.2@211.098,82.917 206.69,83.934 12_OUT_7.2@211.098,84.952 ; 12_OUT_7.2 204.076,83.934 201.93,81.788 198.12,81.788 196.215,83.693 192.151,83.693 191.389,82.931 D17.A
Net12_OUT_8_2: 12_OUT_8.2 12v_08.2 D18.A | length 53.4
  Bottom Layer w1: 12v_08.2 D18.A@191.336,67.843 ; 12v_08.2@184.433,66.849 188.822,67.843 12v_08.2@184.433,68.837 ; 187.625,67.843 D18.A 191.389,69.215 192.226,70.052 195.378,70.052 197.104,68.326 200.914,68.326 206.362,73.774 12_OUT_8.2 ; 12_OUT_8.2@211.098,72.757 206.69,73.774 12_OUT_8.2@211.098,74.792
Net12_OUT_9_2: 12_OUT_9.2 12v_09.2 D19.A | length 51.3
  Bottom Layer w1: 12v_09.2 D19.A@191.324,54.279 ; 12v_09.2@184.433,53.286 188.822,54.279 12v_09.2@184.433,55.273 ; 187.625,54.279 D19.A ; 12_OUT_9.2@211.036,62.606 208.267,63.614 ; 12_OUT_9.2@211.036,64.623 208.267,63.614 ; 12_OUT_9.2 208.267,63.614 ; D19.A 191.389,54.991 ; D19.A 191.389,54.991 ; 191.389,54.991 192.875,56.477 194.931,56.477 195.782,55.626 200.279,55.626 208.267,63.614
Net12_OUT_10_2: 12_OUT_10.2 12v_10.2 D20.A | length 60.2
  Bottom Layer w1: 12v_10.2 D20.A@191.313,40.716 ; 12v_10.2@184.433,39.722 188.822,40.716 12v_10.2@184.433,41.709 ; 187.624,40.716 D20.A 191.389,41.91 192.786,43.307 196.088,43.307 198.12,41.275 200.66,41.275 202.057,42.672 202.057,49.149 206.362,53.454 12_OUT_10.2 ; 12_OUT_10.2@211.098,52.437 206.69,53.454 12_OUT_10.2@211.098,54.472
Net-12_Out_1_1: 1A_01.2 -12_Out_1.1 -12_Out_2.1 D1.A | length 79.4
  Bottom Layer w1: -12_Out_2.1 73.038,158.636 75.438,161.036 75.438,167.005 73.647,168.796 -12_Out_1.1 ; -12_Out_2.1@66.524,157.618 70.932,158.636 -12_Out_2.1@66.524,159.653 ; -12_Out_1.1@66.524,167.778 70.932,168.796 -12_Out_1.1@66.524,169.813 ; 75.438,163.449 78.404,160.483 81.616,160.483 82.818,159.282 85.114,159.282 86.36,160.528 ; 1A_01.2@93.172,162.613 88.799,161.544 ; 1A_01.2@93.206,160.626 88.799,161.544 ; 1A_01.2@93.222,161.544 D1.A ; 1A_01.2 88.799,161.544 ; 86.36,160.528 D1.A ; 86.36,160.528 D1.A
Net-12_Out_3_2: 12v_2A.2 -12_Out_3.2 -12_Out_4.2 D11.A | length 77.6
  Bottom Layer w1: 12v_2A.2 D11.A@191.365,162.79 ; 12v_2A.2@184.433,161.796 188.822,162.79 12v_2A.2@184.433,163.784 ; 187.627,162.79 D11.A 191.389,160.274 191.897,159.766 195.072,159.766 198.945,163.639 203.708,163.639 ; -12_Out_4.2@211.098,157.593 206.69,158.61 -12_Out_4.2@211.098,159.628 ; -12_Out_3.2@211.098,167.753 206.69,168.77 -12_Out_3.2@211.098,169.788 ; -12_Out_4.2 205.499,158.61 203.708,160.401 203.708,163.639 ; -12_Out_3.2 205.6,168.77 203.708,166.878 203.708,163.639
NetD21_K: D21.K R21.1 | length 7.3
  Bottom Layer w1: R21.1 82.55,220.091 83.82,218.821 D21.K
NetD22_K: D22.K R22.1 | length 7
  Bottom Layer w1: R22.1 82.55,206.248 83.82,204.978 D22.K
NetD23_K: D23.K R23.1 | length 6.7
  Bottom Layer w1: R23.1 82.55,192.405 83.82,191.135 D23.K
NetD24_K: D24.K R24.1 | length 9.6
  Bottom Layer w1: R24.1 82.169,170.942 83.82,172.593 ; 83.82,172.593 D24.K 83.82,172.593
NetD25_K: D25.K R25.1 | length 7.7
  Bottom Layer w1: D25.K 193.929,219.964 195.072,221.107 R25.1
NetD26_K: D26.K R26.1 | length 7
  Bottom Layer w1: D26.K 193.929,205.105 196.3,207.476 R26.1
NetD27_K: D27.K R27.1 | length 10.6
  Bottom Layer w1: D27.K 193.929,192.532 195.199,193.802 ; R27.1@198.332,193.802 195.199,193.802 ; R27.1 195.199,193.802
NetD28_K: D28.K R28.1 | length 9.2
  Bottom Layer w1: R28.1 195.707,172.593 193.929,174.371 ; 193.929,174.371 D28.K 193.929,174.371
pads on no net: J1.0 J1.5 J2.0 J2.5

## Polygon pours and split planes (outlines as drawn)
GND on Top Layer "Bottom Layer-No Net" (solid, pour order 6): 226.314,226.314 51.308,226.314 51.308,32.385 226.314,32.385 226.314,226.314

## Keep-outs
Keep-Out Layer:
  lines w0.254: 51.308,32.385 226.314,32.385 226.314,226.314 51.308,226.314 51.308,32.385

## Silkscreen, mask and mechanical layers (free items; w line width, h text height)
Top Overlay:
  text "GND" at 134.874,211.328 h1.52 r270
  text "-12" at 140.97,211.328 h2 r270
  text "GND" at 147.447,211.328 h1.52 r270
  text "+5" at 128.778,211.074 h2 r270
  text "GND" at 148.844,48.641 h2 r90
  text "GND" at 136.525,48.387 h2 r90
  text "+12" at 143.129,48.387 h2 r90
  text "+24" at 130.429,48.26 h2 r90
Bottom Overlay:
  text "GND" at 56.134,203.454 h1.52
  text "GND" at 217.424,203.327 h1.52
  text "GND" at 56.134,193.421 h1.52
  text "GND" at 217.424,193.04 h1.52
  text "GND" at 217.17,183.134 h1.52
  text "GND" at 56.134,182.626 h1.52
  text "GND" at 56.007,173.101 h1.52
  text "GND" at 217.424,172.974 h1.52
  text "GND" at 55.753,162.941 h1.52
  text "GND" at 217.297,162.433 h1.52
  text "GND" at 55.499,152.527 h1.52
  text "GND" at 217.424,152.4 h1.52
  text "GND" at 55.753,138.811 h1.52
  text "GND" at 217.297,138.557 h1.52
  text "GND" at 55.499,129.032 h1.52
  text "GND" at 218.313,128.524 h1.52
  text "GND" at 55.753,118.745 h1.52
  text "GND" at 217.932,118.491 h1.52
  text "GND" at 55.372,108.458 h1.52
  text "GND" at 217.424,108.077 h1.52
  text "GND" at 218.059,98.425 h1.52
  text "GND" at 55.88,98.044 h1.52
  text "GND" at 55.753,88.011 h1.52
  text "GND" at 217.17,88.011 h1.52
  text "GND" at 55.88,77.978 h1.52
  text "GND" at 217.678,77.851 h1.52
  text "GND" at 55.499,68.199 h1.52
  text "GND" at 217.678,67.564 h1.52
  text "GND" at 55.499,57.658 h1.52
  text "GND" at 217.297,57.277 h1.52
  text "GND" at 217.297,47.498 h1.52
  text "GND" at 55.499,47.371 h1.52

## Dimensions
147.955,216.281 to 226.314,226.314 on Mechanical 1
114.3,215.877 to 163.322,217.045 on Mechanical 1
51.308,32.385 to 66.408,48.273 on Mechanical 1
226.314,226.314 to 51.308,226.314 on Mechanical 1
226.314,226.314 to 226.314,32.385 on Mechanical 1
211.214,48.374 to 226.314,32.385 on Mechanical 1
184.322,217.045 to 226.314,226.314 on Mechanical 1
51.308,226.314 to 93.3,215.877 on Mechanical 1
66.408,48.273 to 51.308,32.385 on Mechanical 1
211.214,48.374 to 226.314,32.385 on Mechanical 1
141.955,42.418 to 226.314,32.385 on Mechanical 1
66.408,209.436 to 51.308,226.314 on Mechanical 1
211.214,209.41 to 226.314,226.314 on Mechanical 1
59.309,220.218 to 51.308,226.314 on Mechanical 1
59.309,220.218 to 51.308,226.314 on Mechanical 1
218.313,38.481 to 226.314,32.385 on Mechanical 1
218.313,38.481 to 226.314,32.385 on Mechanical 1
